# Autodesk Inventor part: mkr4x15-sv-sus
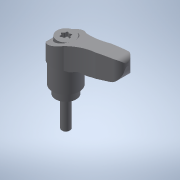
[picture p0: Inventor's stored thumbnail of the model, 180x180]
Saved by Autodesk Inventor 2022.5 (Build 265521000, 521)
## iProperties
Created: 2017-09
Part Number: mkr4x15-sv-sus
Material: 一般
Document SubType Name: Modeling
Designer: imaocorp
Density: 1 g/cm^3
Appearance: 既定
Author: imaocorp
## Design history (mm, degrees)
node "mkr4x15-sv-sus.x_t1"
node "mkr4x15-sv-sus"
node "Base1"
